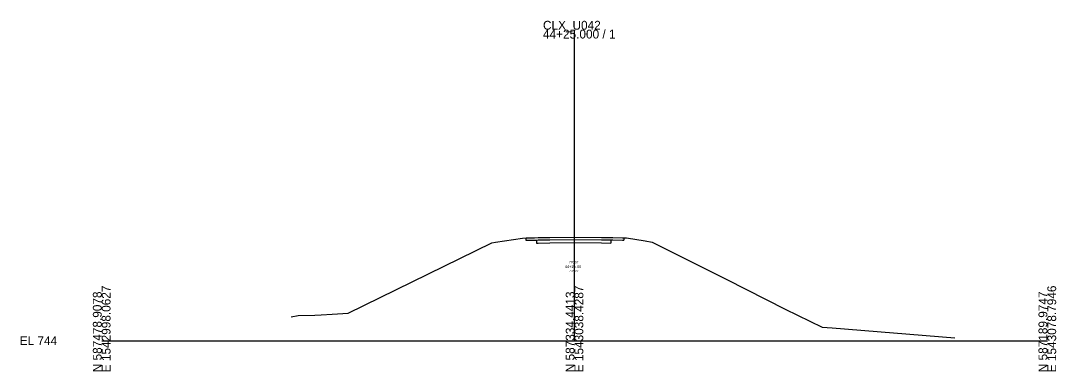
# Model space of a CAD drawing. Extents: x -26 to 1603, y -10 to 5557.
# Drawn here: x -25.7 to 302.8, y 490.3 to 601.5 of the extents above; entities that cross this region are included whole.
import ezdxf

# ---------------------------------------------------------------- set-up
doc = ezdxf.new("R2010")
doc.units = 0
for name, color, linetype in [('GK_Cells', 7, 'Continuous'), ('XS_P_Annotation', 7, 'Continuous'), ('XS_X_Ground_Line', 7, 'Continuous'), ('XS_X_Pavt', 7, 'Continuous')]:
    doc.layers.add(name, color=color, linetype=linetype)

msp = doc.modelspace()

# ---------------------------------------------------------------- linework, layer by layer
at = {"layer": 'GK_Cells'}
for p, q in [((150, 500), (150, 598.62)), ((0, 500), (150, 500)), ((150, 500), (300, 500))]:
    msp.add_line(p, q, dxfattribs=at)
at = {"layer": 'XS_X_Ground_Line'}
msp.add_lwpolyline([(60.16, 507.54), (62.31, 508.04), (67.64, 508.13), (69.62, 508.23), (73.07, 508.42), (78.23, 508.7), (98.48, 518.63), (123.81, 531.03), (124.94, 531.23), (133.48, 532.5), (134.66, 532.64), (137.31, 532.67), (138.51, 532.69), (142.15, 532.75), (150.08, 532.87), (158.51, 532.76), (162.15, 532.71), (165.22, 532.63), (166.45, 532.59), (172.4, 531.62), (174.59, 531.26), (183.5, 526.76), (198.3, 519.37), (216.88, 510.05), (228.52, 504.29), (231.72, 504.06), (270.67, 500.87)], dxfattribs=at)
at = {"layer": 'XS_X_Pavt'}
for p, q in [((134.52, 532.62), (134.52, 531.87)), ((165.6, 532.62), (165.6, 531.87)), ((134.52, 531.87), (134.66, 531.89)), ((134.66, 531.89), (137.31, 531.92)), ((137.31, 531.92), (137.9, 531.93)), ((137.9, 531.93), (138.51, 531.94)), ((137.9, 531.93), (137.9, 530.93)), ((137.9, 530.93), (138.51, 530.94)), ((138.51, 531.94), (142.15, 532)), ((138.51, 530.94), (142.15, 531)), ((142.15, 532), (150.08, 532.12)), ((142.15, 531), (150.08, 531.12)), ((150.08, 532.12), (158.51, 532.01)), ((150.08, 531.12), (158.51, 531.01)), ((158.51, 532.01), (161.51, 531.97)), ((158.51, 531.01), (161.51, 530.97)), ((161.51, 531.97), (162.15, 531.96)), ((161.51, 531.97), (161.51, 530.97)), ((162.15, 531.96), (165.22, 531.88)), ((165.22, 531.88), (165.6, 531.87))]:
    msp.add_line(p, q, dxfattribs=at)

# ---------------------------------------------------------------- texts
at = {"layer": 'GK_Cells'}
for s, p in [('CLX_U042', (140, 598.62)), ('44+25.000 / 1', (140, 595.82)), ('EL 744', (-26, 498.6))]:
    msp.add_text(s, height=2.8, dxfattribs=at).set_placement(p)
for s, p in [('E 1542998.0627', (2.8, 490)), ('E 1543038.4287', (152.8, 490)), ('E 1543078.7946', (302.8, 490)), ('N 587478.9078', (0, 490)), ('N 587334.4413', (150, 490)), ('N 587189.9747', (300, 490))]:
    msp.add_text(s, height=2.8, rotation=90, dxfattribs=at).set_placement(p)
at = {"layer": 'XS_P_Annotation'}
for s, height, p in [('44+25.00', 0.9, (146.94, 523.05)), ('776.87', 0.7, (148.28, 524.55)), ('776.87', 0.7, (148.28, 521.75))]:
    msp.add_text(s, height=height, dxfattribs=at).set_placement(p)

doc.saveas('drawing.dxf')
